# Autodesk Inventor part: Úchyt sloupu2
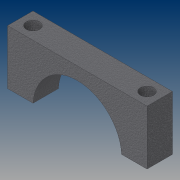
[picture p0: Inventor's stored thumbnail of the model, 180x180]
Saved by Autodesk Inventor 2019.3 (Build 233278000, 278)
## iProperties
Created: 2019-03
Part Number: Úchyt sloupu2
Material: Ocel, legovaná
Document SubType Name: Modeling
Designer: B-hon
Density: 7.73 g/cm^3
Appearance: Železo – lité
Author: B-hon
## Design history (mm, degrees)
sketch "Náčrt1"
  geometry: L1 (-55, 45)-(55, 45); L2 (55, 45)-(55, 0); L3 (-55, 0)-(-55, 45); L4 (55, 0)-(35, 0); L5 (-35, 0)-(-55, 0); A1 r 35 centre (0, 0) between (35, 0) and (-35, 0); 1 further point
  constraints: 10 end point, 3 parallel, 2 horizontal alignment, 2 point on circle, 1 centre point, 1 coincident, 1 horizontal, 1 perpendicular
  dimensions: "d0" = 70 diameter of A1; "d1" = 110 distance of L1.start L1.end; "d2" = 20 distance of L2.end L4.end; "d3" = 45 distance of L1.end L2.end
extrude "Vysunutí1" new body sketch "Náčrt1" distance "d4" = 20; taper "d5" = 0 deg
sketch "Náčrt3"
  geometry: L1 (110, 0)-(110, -20) reference; L2 (110, -20)-(0, -20) reference; 3 further points
  dimensions: "d16" = 90 distance of point (100, -10) point (10, -10); "d17" = 10 distance from line of L1 point (100, -10); "d18" = 10 distance from line of L2 point (100, -10); "d19" = 10 distance from line of L2 point (10, -10)
hole "Díra2" sketch "Náčrt3" at (10, -10), (100, -10) diameter "d20" = 10.5; stored, may be unused: countersink angle "d24" = 90 deg, drill point angle "d26" = 118 deg; dims "d21" = 6, "d22" = 4, "d23" = 2, "d25" = 27.3
node "Upravit přímo1"
node "Těleso1"
feature "Posunout1" dims "d29" = -2
other parameters: "d27" = 0, "d28" = 0
